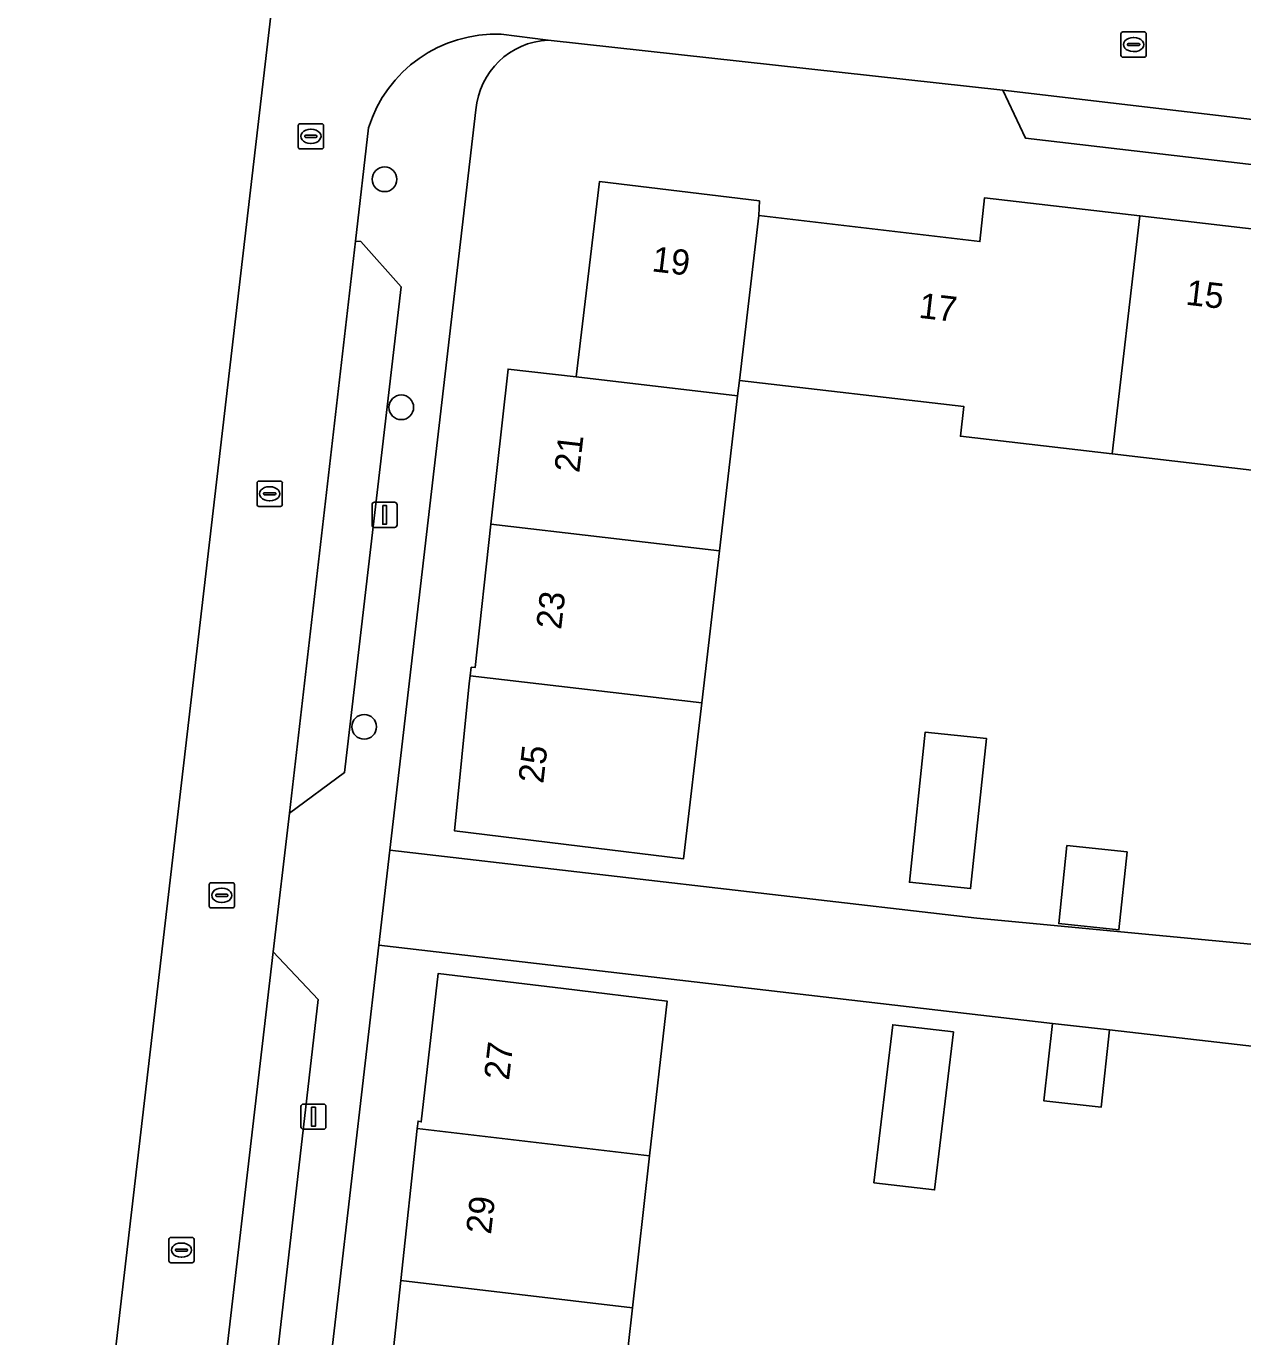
# Model space of a CAD drawing. Extents: x 161241 to 161758, y 384138 to 384885.
# Drawn here: x 161339.7 to 161387.9, y 384527.4 to 384579.4 of the extents above; entities that cross this region are included whole.
import ezdxf

# ---------------------------------------------------------------- set-up
doc = ezdxf.new("R2010")
doc.units = 0
for name, color, linetype in [('IMGEO_Boom', 7, 'Continuous'), ('IMGEO_Erf', 7, 'Continuous'), ('IMGEO_Kolk', 7, 'Continuous'), ('IMGEO_Lichtmast', 7, 'Continuous'), ('IMGEO_Pand', 7, 'Continuous'), ('IMGEO_Pand_nummerreeks', 7, 'Continuous'), ('IMGEO_Parkeervlak_open', 7, 'Continuous'), ('IMGEO_Rijbaan_lokaal_open', 7, 'Continuous'), ('IMGEO_Voetpad_open', 7, 'Continuous')]:
    doc.layers.add(name, color=color, linetype=linetype)

msp = doc.modelspace()

# ---------------------------------------------------------------- linework, layer by layer
at = {"layer": 'IMGEO_Boom'}
for centre in [(161353.865, 384573.311), (161354.528, 384564.274), (161353.058, 384551.609)]:
    msp.add_circle(centre, 0.489, dxfattribs=at)
at = {"layer": 'IMGEO_Erf'}
for points in [[(161332.131, 384432.245), (161332.897, 384438.907), (161336.632, 384471.394), (161336.946, 384474.139), (161340.403, 384504.377), (161340.647, 384506.515), (161340.82, 384506.489), (161349.943, 384584.816), (161350.191, 384586.943), (161382.92, 384583.217)], [(161414.97, 384570.779), (161379.272, 384574.949), (161378.37, 384576.849), (161360.348, 384578.831)], [(161357.485, 384576.07), (161354.08, 384546.72), (161377.34, 384544.021), (161390.293, 384542.794), (161390.36, 384543.501), (161390.582, 384545.866), (161392.883, 384545.649), (161395.45, 384545.408), (161395.217, 384542.927), (161395.161, 384542.336), (161402.036, 384541.672), (161402.295, 384544.437), (161402.53, 384544.415), (161404.855, 384544.197), (161407.398, 384543.958), (161407.123, 384541.032), (161411.359, 384540.633), (161414.97, 384570.779)], [(161388.693, 384561.726), (161382.705, 384562.426), (161376.693, 384563.128), (161376.83, 384564.3), (161367.93, 384565.34), (161367.859, 384564.73), (161367.141, 384558.583), (161366.438, 384552.56), (161365.715, 384546.372), (161361.603, 384546.876), (161356.64, 384547.484), (161357.225, 384553.321), (161357.263, 384553.636), (161357.303, 384553.969), (161357.453, 384553.958), (161358.082, 384559.645), (161358.761, 384565.791), (161361.464, 384565.476), (161362.382, 384573.219), (161368.724, 384572.458), (161368.697, 384571.871), (161377.466, 384570.841), (161377.65, 384572.579), (161383.809, 384571.858), (161389.798, 384571.158)], [(161425.565, 384524.36), (161426.026, 384528.384), (161423.722, 384528.608), (161421.212, 384528.819), (161421.738, 384535.09), (161419.21, 384535.381), (161406.432, 384536.854), (161406.08, 384533.855), (161403.791, 384534.055), (161401.206, 384534.28), (161401.474, 384537.359), (161394.449, 384538.235), (161394.187, 384535.23), (161391.807, 384535.437), (161389.352, 384535.651), (161389.625, 384538.791), (161382.609, 384539.597), (161382.266, 384536.529), (161379.995, 384536.783), (161380.337, 384539.851), (161353.642, 384542.948), (161349.844, 384510.209)], [(161353.849, 384523.505), (161354.513, 384529.66), (161355.163, 384535.687), (161355.195, 384535.982), (161355.319, 384535.95), (161355.989, 384541.828), (161360.954, 384541.232), (161365.062, 384540.738), (161364.373, 384534.605), (161363.697, 384528.581), (161363.009, 384522.448)]]:
    msp.add_lwpolyline(points, dxfattribs=at)
for points in [[(161374.67, 384545.446), (161375.302, 384551.397), (161377.728, 384551.139), (161377.098, 384545.197)], [(161380.915, 384546.899), (161383.297, 384546.65), (161382.973, 384543.56), (161380.592, 384543.81)], [(161373.265, 384533.537), (161374.01, 384539.798), (161376.416, 384539.512), (161375.67, 384533.25)]]:
    msp.add_lwpolyline(points, close=True, dxfattribs=at)
msp.add_arc((161360.507, 384575.801), 3.034, 93.0098, 174.9122, dxfattribs=at)
at = {"layer": 'IMGEO_Kolk'}
for p, q in [((161383.057, 384578.228), (161383.057, 384579.08)), ((161383.132, 384579.154), (161383.984, 384579.154)), ((161383.545, 384578.934), (161383.57, 384578.934)), ((161384.058, 384579.08), (161384.058, 384578.228)), ((161383.316, 384578.648), (161383.316, 384578.66)), ((161383.754, 384578.611), (161383.356, 384578.611)), ((161383.359, 384578.697), (161383.757, 384578.697)), ((161383.8, 384578.66), (161383.8, 384578.648)), ((161383.984, 384578.154), (161383.132, 384578.154)), ((161383.568, 384578.374), (161383.543, 384578.374)), ((161350.444, 384574.588), (161350.444, 384575.44)), ((161350.519, 384575.514), (161351.371, 384575.514)), ((161350.932, 384575.294), (161350.957, 384575.294)), ((161351.445, 384575.44), (161351.445, 384574.588)), ((161350.703, 384575.008), (161350.703, 384575.02)), ((161351.141, 384574.971), (161350.743, 384574.971)), ((161350.746, 384575.057), (161351.144, 384575.057)), ((161351.187, 384575.02), (161351.187, 384575.008)), ((161351.371, 384574.514), (161350.519, 384574.514)), ((161350.955, 384574.734), (161350.93, 384574.734)), ((161348.812, 384560.42), (161348.812, 384561.272)), ((161348.887, 384561.346), (161349.739, 384561.346)), ((161349.813, 384561.272), (161349.813, 384560.42)), ((161349.071, 384560.84), (161349.071, 384560.852)), ((161349.509, 384560.803), (161349.111, 384560.803)), ((161349.114, 384560.889), (161349.512, 384560.889)), ((161349.3, 384561.126), (161349.325, 384561.126)), ((161349.555, 384560.852), (161349.555, 384560.84)), ((161349.739, 384560.346), (161348.887, 384560.346)), ((161349.323, 384560.566), (161349.298, 384560.566)), ((161346.913, 384544.502), (161346.913, 384545.354)), ((161346.988, 384545.428), (161347.84, 384545.428)), ((161347.401, 384545.208), (161347.426, 384545.208)), ((161347.914, 384545.354), (161347.914, 384544.502)), ((161347.172, 384544.922), (161347.172, 384544.934)), ((161347.61, 384544.885), (161347.212, 384544.885)), ((161347.215, 384544.971), (161347.613, 384544.971)), ((161347.424, 384544.648), (161347.399, 384544.648)), ((161347.656, 384544.934), (161347.656, 384544.922)), ((161347.84, 384544.428), (161346.988, 384544.428)), ((161345.316, 384530.44), (161345.316, 384531.292)), ((161345.391, 384531.366), (161346.243, 384531.366)), ((161345.804, 384531.146), (161345.829, 384531.146)), ((161346.317, 384531.292), (161346.317, 384530.44)), ((161345.575, 384530.86), (161345.575, 384530.872)), ((161346.013, 384530.823), (161345.615, 384530.823)), ((161345.618, 384530.909), (161346.016, 384530.909)), ((161345.827, 384530.586), (161345.802, 384530.586)), ((161346.059, 384530.872), (161346.059, 384530.86)), ((161346.243, 384530.366), (161345.391, 384530.366))]:
    msp.add_line(p, q, dxfattribs=at)
for points in [[(161383.057, 384578.228), (161383.057, 384579.08)], [(161383.132, 384579.154), (161383.984, 384579.154)], [(161384.058, 384579.08), (161384.058, 384578.228)], [(161383.984, 384578.154), (161383.132, 384578.154)], [(161350.444, 384574.588), (161350.444, 384575.44)], [(161350.519, 384575.514), (161351.371, 384575.514)], [(161351.445, 384575.44), (161351.445, 384574.588)], [(161351.371, 384574.514), (161350.519, 384574.514)], [(161348.812, 384560.42), (161348.812, 384561.272)], [(161348.887, 384561.346), (161349.739, 384561.346)], [(161349.813, 384561.272), (161349.813, 384560.42)], [(161349.739, 384560.346), (161348.887, 384560.346)], [(161346.913, 384544.502), (161346.913, 384545.354)], [(161346.988, 384545.428), (161347.84, 384545.428)], [(161347.914, 384545.354), (161347.914, 384544.502)], [(161347.84, 384544.428), (161346.988, 384544.428)], [(161345.316, 384530.44), (161345.316, 384531.292)], [(161345.391, 384531.366), (161346.243, 384531.366)], [(161346.317, 384531.292), (161346.317, 384530.44)], [(161346.243, 384530.366), (161345.391, 384530.366)]]:
    msp.add_lwpolyline(points, dxfattribs=at)
for centre, radius, start, end in [((161383.134, 384579.078), 0.0765, 91.552, 178.448), ((161383.134, 384579.078), 0.0765, 91.552, 178.448), ((161383.982, 384579.078), 0.0765, 1.552, 88.448), ((161383.982, 384579.078), 0.0765, 1.552, 88.448), ((161383.356, 384578.657), 0.0403, 85.8775, 175.7526), ((161383.353, 384578.647), 0.0366, 178.938, 274.7102), ((161383.757, 384578.654), 0.043, 264.8664, 352.4533), ((161383.761, 384578.659), 0.0386, 1.7309, 96.639), ((161383.134, 384578.23), 0.0765, 181.552, 268.448), ((161383.134, 384578.23), 0.0765, 181.552, 268.448), ((161383.982, 384578.23), 0.0765, 271.552, 358.448), ((161383.982, 384578.23), 0.0765, 271.552, 358.448), ((161350.521, 384575.438), 0.0765, 91.552, 178.448), ((161350.521, 384575.438), 0.0765, 91.552, 178.448), ((161351.369, 384575.438), 0.0765, 1.552, 88.448), ((161351.369, 384575.438), 0.0765, 1.552, 88.448), ((161350.743, 384575.017), 0.0403, 85.8775, 175.7526), ((161350.74, 384575.007), 0.0366, 178.938, 274.7102), ((161351.144, 384575.014), 0.043, 264.8664, 352.4533), ((161351.148, 384575.019), 0.0386, 1.7309, 96.639), ((161350.521, 384574.59), 0.0765, 181.552, 268.448), ((161350.521, 384574.59), 0.0765, 181.552, 268.448), ((161351.369, 384574.59), 0.0765, 271.552, 358.448), ((161351.369, 384574.59), 0.0765, 271.552, 358.448), ((161348.889, 384561.27), 0.0765, 91.552, 178.448), ((161348.889, 384561.27), 0.0765, 91.552, 178.448), ((161349.737, 384561.27), 0.0765, 1.552, 88.448), ((161349.737, 384561.27), 0.0765, 1.552, 88.448), ((161349.111, 384560.849), 0.0403, 85.8775, 175.7526), ((161349.108, 384560.839), 0.0366, 178.938, 274.7102), ((161349.512, 384560.846), 0.043, 264.8664, 352.4533), ((161349.516, 384560.851), 0.0386, 1.7309, 96.639), ((161348.889, 384560.422), 0.0765, 181.552, 268.448), ((161348.889, 384560.422), 0.0765, 181.552, 268.448), ((161349.737, 384560.422), 0.0765, 271.552, 358.448), ((161349.737, 384560.422), 0.0765, 271.552, 358.448), ((161346.99, 384545.352), 0.0765, 91.552, 178.448), ((161346.99, 384545.352), 0.0765, 91.552, 178.448), ((161347.838, 384545.352), 0.0765, 1.552, 88.448), ((161347.838, 384545.352), 0.0765, 1.552, 88.448), ((161347.212, 384544.931), 0.0403, 85.8775, 175.7526), ((161347.209, 384544.921), 0.0366, 178.938, 274.7102), ((161347.613, 384544.928), 0.043, 264.8664, 352.4533), ((161347.617, 384544.933), 0.0386, 1.7309, 96.639), ((161346.99, 384544.504), 0.0765, 181.552, 268.448), ((161346.99, 384544.504), 0.0765, 181.552, 268.448), ((161347.838, 384544.504), 0.0765, 271.552, 358.448), ((161347.838, 384544.504), 0.0765, 271.552, 358.448), ((161345.393, 384531.29), 0.0765, 91.552, 178.448), ((161345.393, 384531.29), 0.0765, 91.552, 178.448), ((161346.241, 384531.29), 0.0765, 1.552, 88.448), ((161346.241, 384531.29), 0.0765, 1.552, 88.448), ((161345.615, 384530.869), 0.0403, 85.8775, 175.7526), ((161345.612, 384530.859), 0.0366, 178.938, 274.7102), ((161346.016, 384530.866), 0.043, 264.8664, 352.4533), ((161346.02, 384530.871), 0.0386, 1.7309, 96.639), ((161345.393, 384530.442), 0.0765, 181.552, 268.448), ((161345.393, 384530.442), 0.0765, 181.552, 268.448), ((161346.241, 384530.442), 0.0765, 271.552, 358.448), ((161346.241, 384530.442), 0.0765, 271.552, 358.448)]:
    msp.add_arc(centre, radius, start, end, dxfattribs=at)
for centre, major_axis, ratio, start_param, end_param in [((161383.544, 384578.654), (-0.387, 0.002), 0.722429, 4.712389, 7.853982), ((161383.569, 384578.654), (-0.39, 0.002), 0.717154, 1.570796, 4.712389), ((161350.931, 384575.014), (-0.387, 0.002), 0.722429, 4.712389, 7.853982), ((161350.956, 384575.014), (-0.39, 0.002), 0.717154, 1.570796, 4.712389), ((161349.299, 384560.846), (-0.387, 0.002), 0.722429, 4.712389, 7.853982), ((161349.324, 384560.846), (-0.39, 0.002), 0.717154, 1.570796, 4.712389), ((161347.4, 384544.928), (-0.387, 0.002), 0.722429, 4.712389, 7.853982), ((161347.425, 384544.928), (-0.39, 0.002), 0.717154, 1.570796, 4.712389), ((161345.803, 384530.866), (-0.387, 0.002), 0.722429, 4.712389, 7.853982), ((161345.828, 384530.866), (-0.39, 0.002), 0.717154, 1.570796, 4.712389)]:
    msp.add_ellipse(centre, major_axis=major_axis, ratio=ratio, start_param=start_param, end_param=end_param, dxfattribs=at)
at = {"layer": 'IMGEO_Lichtmast'}
for p, q in [((161353.371, 384559.611), (161353.371, 384560.411)), ((161353.371, 384560.411), (161353.371, 384559.611)), ((161353.471, 384560.511), (161354.261, 384560.511)), ((161354.261, 384560.511), (161353.471, 384560.511)), ((161354.361, 384560.411), (161354.361, 384559.611)), ((161354.361, 384559.611), (161354.361, 384560.411)), ((161354.261, 384559.511), (161353.471, 384559.511)), ((161353.471, 384559.511), (161354.261, 384559.511)), ((161350.552, 384535.753), (161350.552, 384536.553)), ((161350.552, 384536.553), (161350.552, 384535.753)), ((161350.652, 384536.653), (161351.442, 384536.653)), ((161351.442, 384536.653), (161350.652, 384536.653)), ((161351.542, 384536.553), (161351.542, 384535.753)), ((161351.542, 384535.753), (161351.542, 384536.553)), ((161351.442, 384535.653), (161350.652, 384535.653)), ((161350.652, 384535.653), (161351.442, 384535.653))]:
    msp.add_line(p, q, dxfattribs=at)
for points in [[(161353.791, 384560.386), (161353.941, 384560.386), (161353.941, 384559.636), (161353.791, 384559.636), (161353.791, 384560.386)], [(161350.972, 384536.528), (161351.122, 384536.528), (161351.122, 384535.778), (161350.972, 384535.778), (161350.972, 384536.528)]]:
    msp.add_lwpolyline(points, dxfattribs=at)
for centre, start, end in [((161353.471, 384560.411), 90, 180), ((161353.471, 384560.411), 90, 180), ((161354.261, 384560.411), 0, 90), ((161354.261, 384560.411), 360, 90), ((161353.471, 384559.611), 180, 270), ((161353.471, 384559.611), 180, 270), ((161354.261, 384559.611), 270, 0), ((161354.261, 384559.611), 270, 0), ((161350.652, 384536.553), 90, 180), ((161350.652, 384536.553), 90, 180), ((161351.442, 384536.553), 0, 90), ((161351.442, 384536.553), 360, 90), ((161350.652, 384535.753), 180, 270), ((161350.652, 384535.753), 180, 270), ((161351.442, 384535.753), 270, 0), ((161351.442, 384535.753), 270, 0)]:
    msp.add_arc(centre, 0.1, start, end, dxfattribs=at)
at = {"layer": 'IMGEO_Pand'}
for points in [[(161367.859, 384564.73), (161367.93, 384565.34), (161368.697, 384571.871), (161368.724, 384572.458), (161362.382, 384573.219), (161361.464, 384565.476)], [(161383.809, 384571.858), (161377.65, 384572.579), (161377.466, 384570.841), (161368.697, 384571.871), (161367.93, 384565.34), (161376.83, 384564.3), (161376.693, 384563.128), (161382.705, 384562.426)], [(161382.705, 384562.426), (161388.693, 384561.726), (161389.798, 384571.158), (161383.809, 384571.858)], [(161361.464, 384565.476), (161358.761, 384565.791), (161358.082, 384559.645), (161367.141, 384558.583), (161367.859, 384564.73)], [(161366.438, 384552.56), (161367.141, 384558.583), (161358.082, 384559.645), (161357.453, 384553.958), (161357.303, 384553.969), (161357.263, 384553.636)], [(161357.263, 384553.636), (161357.225, 384553.321), (161356.64, 384547.484), (161361.603, 384546.876), (161365.715, 384546.372), (161366.438, 384552.56)], [(161375.302, 384551.397), (161374.67, 384545.446), (161377.098, 384545.197), (161377.728, 384551.139)], [(161380.915, 384546.899), (161380.592, 384543.81), (161382.973, 384543.56), (161383.297, 384546.65)], [(161364.373, 384534.605), (161365.062, 384540.738), (161360.954, 384541.232), (161355.989, 384541.828), (161355.319, 384535.95), (161355.195, 384535.982), (161355.163, 384535.687)], [(161373.265, 384533.537), (161375.67, 384533.25), (161376.416, 384539.512), (161374.01, 384539.798)], [(161382.609, 384539.597), (161380.337, 384539.851), (161379.995, 384536.783), (161382.266, 384536.529)], [(161363.697, 384528.581), (161364.373, 384534.605), (161355.163, 384535.687), (161354.513, 384529.66)], [(161354.513, 384529.66), (161353.849, 384523.505), (161356.534, 384523.195), (161363.009, 384522.448), (161363.697, 384528.581)]]:
    msp.add_lwpolyline(points, close=True, dxfattribs=at)
at = {"layer": 'IMGEO_Parkeervlak_open'}
for points in [[(161378.37, 384576.849), (161379.272, 384574.949), (161414.97, 384570.779), (161415.137, 384572.53)], [(161352.715, 384570.865), (161350.099, 384548.19), (161352.281, 384549.796), (161354.523, 384569.051), (161352.928, 384570.84)], [(161346.902, 384520.776), (161349.128, 384522.508), (161351.24, 384540.794), (161349.456, 384542.683)]]:
    msp.add_lwpolyline(points, close=True, dxfattribs=at)
at = {"layer": 'IMGEO_Rijbaan_lokaal_open'}
for points in [[(161382.841, 384581.101), (161349.943, 384584.816), (161340.82, 384506.489), (161354.376, 384504.9), (161354.929, 384509.609), (161349.844, 384510.209)], [(161358.492, 384579.061), (161360.348, 384578.831), (161378.37, 384576.849), (161415.137, 384572.53), (161414.97, 384570.779), (161418.982, 384570.31), (161419.169, 384572.05), (161432.118, 384570.547), (161450.255, 384568.412), (161450.399, 384568.382), (161450.927, 384573.072), (161397.745, 384579.321)], [(161346.307, 384515.385), (161346.902, 384520.776), (161349.456, 384542.683), (161350.099, 384548.19), (161352.715, 384570.865), (161353.233, 384575.354)], [(161390.293, 384542.794), (161377.34, 384544.021), (161354.08, 384546.72), (161353.642, 384542.948), (161380.337, 384539.851), (161382.609, 384539.597), (161389.625, 384538.791)]]:
    msp.add_lwpolyline(points, dxfattribs=at)
msp.add_arc((161358.272, 384573.79), 5.276, 87.6055, 162.7535, dxfattribs=at)
at = {"layer": 'IMGEO_Voetpad_open'}
for points in [[(161360.348, 384578.831), (161358.492, 384579.061)], [(161354.08, 384546.72), (161357.485, 384576.07)], [(161353.233, 384575.354), (161352.715, 384570.865), (161352.928, 384570.84), (161354.523, 384569.051), (161352.281, 384549.796), (161350.099, 384548.19), (161349.456, 384542.683), (161351.24, 384540.794), (161349.128, 384522.508), (161346.902, 384520.776), (161346.307, 384515.385)], [(161349.844, 384510.209), (161353.642, 384542.948), (161354.08, 384546.72)]]:
    msp.add_lwpolyline(points, dxfattribs=at)
for centre, radius, start, end in [((161358.272, 384573.79), 5.276, 87.6055, 162.7535), ((161360.507, 384575.801), 3.034, 93.0098, 174.9122)]:
    msp.add_arc(centre, radius, start, end, dxfattribs=at)

# ---------------------------------------------------------------- texts
at = {"layer": 'IMGEO_Pand_nummerreeks'}
for s, rotation, p in [('19', 353.1576, (161364.431, 384569.669)), ('15', 353.3276, (161385.595, 384568.347)), ('17', 353.3, (161375.013, 384567.826)), ('21', 83.3913, (161361.583, 384561.654)), ('23', 83.3913, (161360.863, 384555.439)), ('25', 83.3913, (161360.156, 384549.336)), ('27', 83.3384, (161358.795, 384537.573)), ('29', 83.3384, (161358.081, 384531.465))]:
    msp.add_text(s, height=1, rotation=rotation, dxfattribs=at).set_placement(p)

doc.saveas('drawing.dxf')
